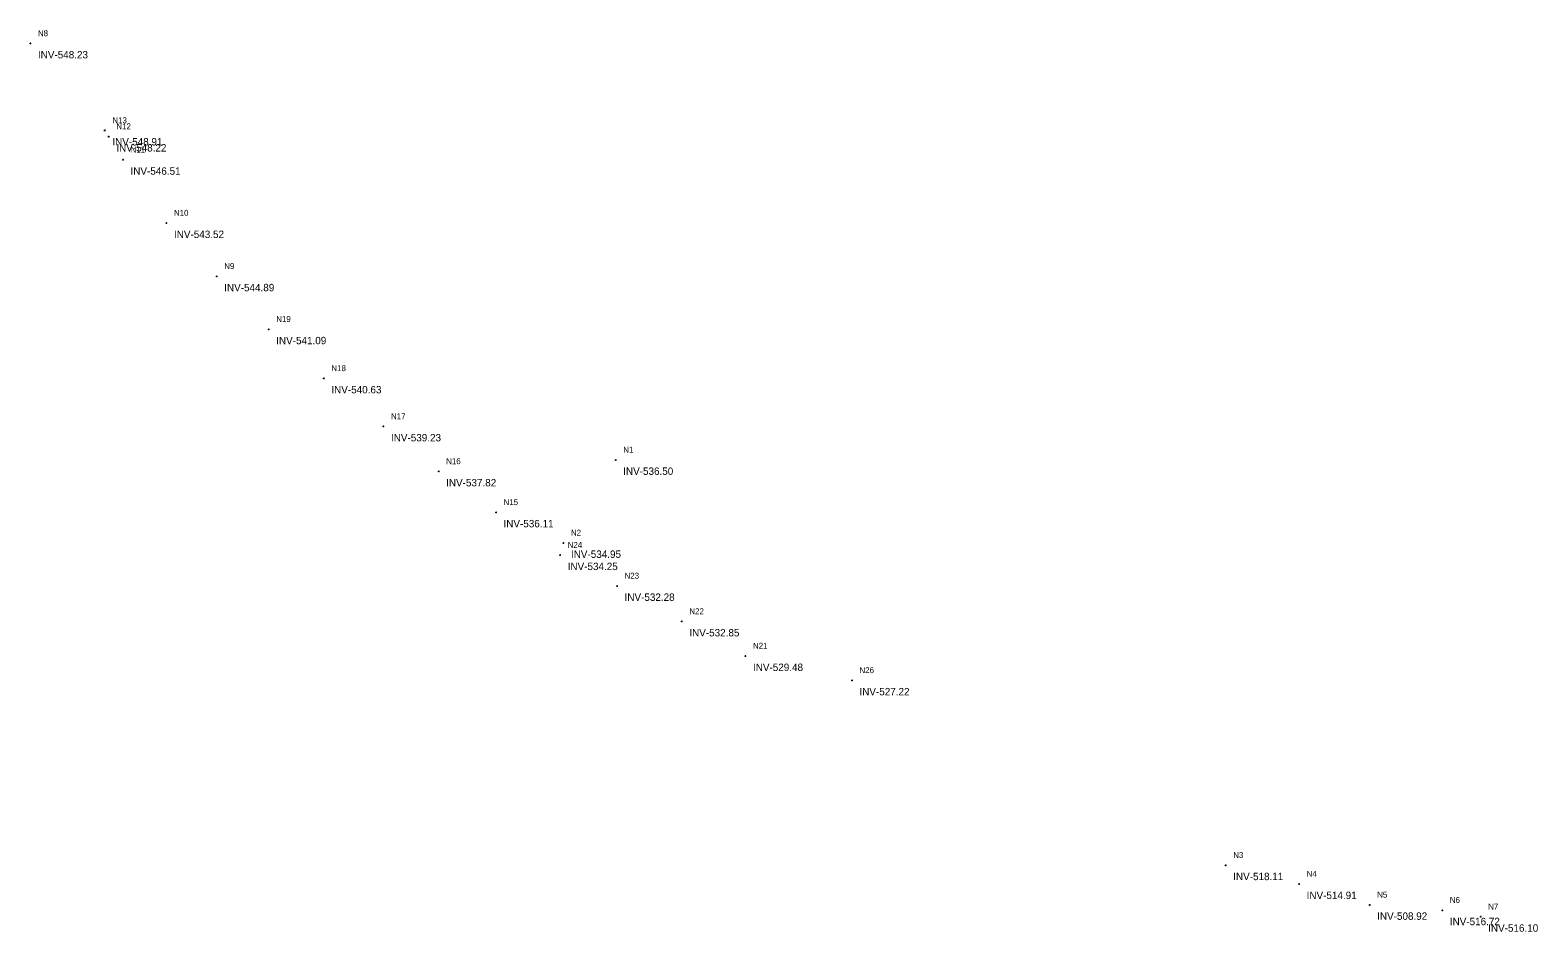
# Model space of a CAD drawing. Extents: x 1732262 to 1733280, y 649887 to 650496.
import ezdxf

# ---------------------------------------------------------------- set-up
doc = ezdxf.new("R2010")
doc.units = 0
for name, color, linetype in [('SURVEY - DRAINAGE - Storm Sewer - Points - Elevations', 7, 'Continuous'), ('SURVEY - DRAINAGE - Storm Sewer - Points - Locators', 7, 'Continuous'), ('SURVEY - DRAINAGE - Storm Sewer - Points - Numbers', 7, 'Continuous')]:
    doc.layers.add(name, color=color, linetype=linetype)

msp = doc.modelspace()

# ---------------------------------------------------------------- linework, layer by layer
at = {"layer": 'SURVEY - DRAINAGE - Storm Sewer - Points - Locators'}
for p, q in [((1732262.35, 650486.64), (1732261.85, 650486.64)), ((1732262.1, 650486.39), (1732262.1, 650486.89)), ((1732262.1, 650486.64), (1732262.1, 650486.64)), ((1732262.1, 650486.64), (1732262.1, 650486.64)), ((1732312.64, 650427.85), (1732312.14, 650427.85)), ((1732312.39, 650427.6), (1732312.39, 650428.1)), ((1732312.39, 650427.85), (1732312.39, 650427.85)), ((1732312.39, 650427.85), (1732312.39, 650427.85)), ((1732315.33, 650423.77), (1732314.83, 650423.77)), ((1732315.08, 650423.52), (1732315.08, 650424.02)), ((1732315.08, 650423.77), (1732315.08, 650423.77)), ((1732315.08, 650423.77), (1732315.08, 650423.77)), ((1732324.9, 650408.08), (1732324.4, 650408.08)), ((1732324.65, 650407.83), (1732324.65, 650408.33)), ((1732324.65, 650408.08), (1732324.65, 650408.08)), ((1732324.65, 650408.08), (1732324.65, 650408.08)), ((1732354.25, 650365.36), (1732353.75, 650365.36)), ((1732354, 650365.11), (1732354, 650365.61)), ((1732354, 650365.36), (1732354, 650365.36)), ((1732354, 650365.36), (1732354, 650365.36)), ((1732388.2, 650329.4), (1732387.7, 650329.4)), ((1732387.95, 650329.15), (1732387.95, 650329.65)), ((1732387.95, 650329.4), (1732387.95, 650329.4)), ((1732387.95, 650329.4), (1732387.95, 650329.4)), ((1732423.32, 650293.63), (1732422.82, 650293.63)), ((1732423.07, 650293.38), (1732423.07, 650293.88)), ((1732423.07, 650293.63), (1732423.07, 650293.63)), ((1732423.07, 650293.63), (1732423.07, 650293.63)), ((1732460.58, 650260.47), (1732460.08, 650260.47)), ((1732460.33, 650260.22), (1732460.33, 650260.72)), ((1732460.33, 650260.47), (1732460.33, 650260.47)), ((1732460.33, 650260.47), (1732460.33, 650260.47)), ((1732500.84, 650228.04), (1732500.34, 650228.04)), ((1732500.59, 650227.79), (1732500.59, 650228.29)), ((1732500.59, 650228.04), (1732500.59, 650228.04)), ((1732500.59, 650228.04), (1732500.59, 650228.04)), ((1732538.1, 650197.66), (1732537.6, 650197.66)), ((1732537.85, 650197.41), (1732537.85, 650197.91)), ((1732537.85, 650197.66), (1732537.85, 650197.66)), ((1732537.85, 650197.66), (1732537.85, 650197.66)), ((1732657.71, 650205.43), (1732657.21, 650205.43)), ((1732657.46, 650205.18), (1732657.46, 650205.68)), ((1732657.46, 650205.43), (1732657.46, 650205.43)), ((1732657.46, 650205.43), (1732657.46, 650205.43)), ((1732576.86, 650170.01), (1732576.36, 650170.01)), ((1732576.61, 650169.76), (1732576.61, 650170.26)), ((1732576.61, 650170.01), (1732576.61, 650170.01)), ((1732576.61, 650170.01), (1732576.61, 650170.01)), ((1732622.41, 650149.38), (1732621.91, 650149.38)), ((1732622.16, 650149.13), (1732622.16, 650149.63)), ((1732622.16, 650149.38), (1732622.16, 650149.38)), ((1732622.16, 650149.38), (1732622.16, 650149.38)), ((1732620.21, 650141.14), (1732619.71, 650141.14)), ((1732619.96, 650140.89), (1732619.96, 650141.39)), ((1732619.96, 650141.14), (1732619.96, 650141.14)), ((1732619.96, 650141.14), (1732619.96, 650141.14)), ((1732658.64, 650120.35), (1732658.14, 650120.35)), ((1732658.39, 650120.1), (1732658.39, 650120.6)), ((1732658.39, 650120.35), (1732658.39, 650120.35)), ((1732658.39, 650120.35), (1732658.39, 650120.35)), ((1732702.39, 650096.35), (1732701.89, 650096.35)), ((1732702.14, 650096.1), (1732702.14, 650096.6)), ((1732702.14, 650096.35), (1732702.14, 650096.35)), ((1732702.14, 650096.35), (1732702.14, 650096.35)), ((1732745.37, 650073.01), (1732744.87, 650073.01)), ((1732745.12, 650072.76), (1732745.12, 650073.26)), ((1732745.12, 650073.01), (1732745.12, 650073.01)), ((1732745.12, 650073.01), (1732745.12, 650073.01)), ((1732817.3, 650056.58), (1732816.8, 650056.58)), ((1732817.05, 650056.33), (1732817.05, 650056.83)), ((1732817.05, 650056.58), (1732817.05, 650056.58)), ((1732817.05, 650056.58), (1732817.05, 650056.58)), ((1733069.79, 649931.78), (1733069.29, 649931.78)), ((1733069.54, 649931.53), (1733069.54, 649932.03)), ((1733069.54, 649931.78), (1733069.54, 649931.78)), ((1733069.54, 649931.78), (1733069.54, 649931.78)), ((1733119.37, 649919.04), (1733118.87, 649919.04)), ((1733119.12, 649918.79), (1733119.12, 649919.29)), ((1733119.12, 649919.04), (1733119.12, 649919.04)), ((1733119.12, 649919.04), (1733119.12, 649919.04)), ((1733167.02, 649905), (1733166.52, 649905)), ((1733166.77, 649904.75), (1733166.77, 649905.25)), ((1733166.77, 649905), (1733166.77, 649905)), ((1733166.77, 649905), (1733166.77, 649905)), ((1733216.1, 649901.38), (1733215.6, 649901.38)), ((1733215.85, 649901.13), (1733215.85, 649901.63)), ((1733215.85, 649901.38), (1733215.85, 649901.38)), ((1733215.85, 649901.38), (1733215.85, 649901.38)), ((1733242, 649896.96), (1733241.5, 649896.96)), ((1733241.75, 649896.71), (1733241.75, 649897.21)), ((1733241.75, 649896.96), (1733241.75, 649896.96)), ((1733241.75, 649896.96), (1733241.75, 649896.96))]:
    msp.add_line(p, q, dxfattribs=at)

# ---------------------------------------------------------------- texts
at = {"layer": 'SURVEY - DRAINAGE - Storm Sewer - Points - Elevations'}
for s, p in [('INV-548.23', (1732267.1, 650476.64)), ('INV-548.91', (1732317.39, 650417.85)), ('INV-548.22', (1732320.08, 650413.77)), ('INV-546.51', (1732329.65, 650398.08)), ('INV-543.52', (1732359, 650355.36)), ('INV-544.89', (1732392.95, 650319.4)), ('INV-541.09', (1732428.07, 650283.63)), ('INV-540.63', (1732465.33, 650250.47)), ('INV-539.23', (1732505.59, 650218.04)), ('INV-536.50', (1732662.46, 650195.43)), ('INV-537.82', (1732542.85, 650187.66)), ('INV-536.11', (1732581.61, 650160.01)), ('INV-534.25', (1732624.96, 650131.14)), ('INV-534.95', (1732627.16, 650139.38)), ('INV-532.28', (1732663.39, 650110.35)), ('INV-532.85', (1732707.14, 650086.35)), ('INV-529.48', (1732750.12, 650063.01)), ('INV-527.22', (1732822.05, 650046.58)), ('INV-518.11', (1733074.54, 649921.78)), ('INV-514.91', (1733124.12, 649909.04)), ('INV-508.92', (1733171.77, 649895)), ('INV-516.72', (1733220.85, 649891.38)), ('INV-516.10', (1733246.75, 649886.96))]:
    msp.add_text(s, height=5, dxfattribs=at).set_placement(p)
at = {"layer": 'SURVEY - DRAINAGE - Storm Sewer - Points - Numbers'}
for s, p in [('N8', (1732267.1, 650491.64)), ('N13', (1732317.39, 650432.85)), ('N12', (1732320.08, 650428.77)), ('N11', (1732329.65, 650413.08)), ('N10', (1732359, 650370.36)), ('N9', (1732392.95, 650334.4)), ('N19', (1732428.07, 650298.63)), ('N18', (1732465.33, 650265.47)), ('N17', (1732505.59, 650233.04)), ('N16', (1732542.85, 650202.66)), ('N1', (1732662.46, 650210.43)), ('N15', (1732581.61, 650175.01)), ('N2', (1732627.16, 650154.38)), ('N24', (1732624.96, 650146.14)), ('N23', (1732663.39, 650125.35)), ('N22', (1732707.14, 650101.35)), ('N21', (1732750.12, 650078.01)), ('N26', (1732822.05, 650061.58)), ('N3', (1733074.54, 649936.78)), ('N4', (1733124.12, 649924.04)), ('N5', (1733171.77, 649910)), ('N6', (1733220.85, 649906.38)), ('N7', (1733246.75, 649901.96))]:
    msp.add_text(s, height=4, dxfattribs=at).set_placement(p)

doc.saveas('drawing.dxf')
